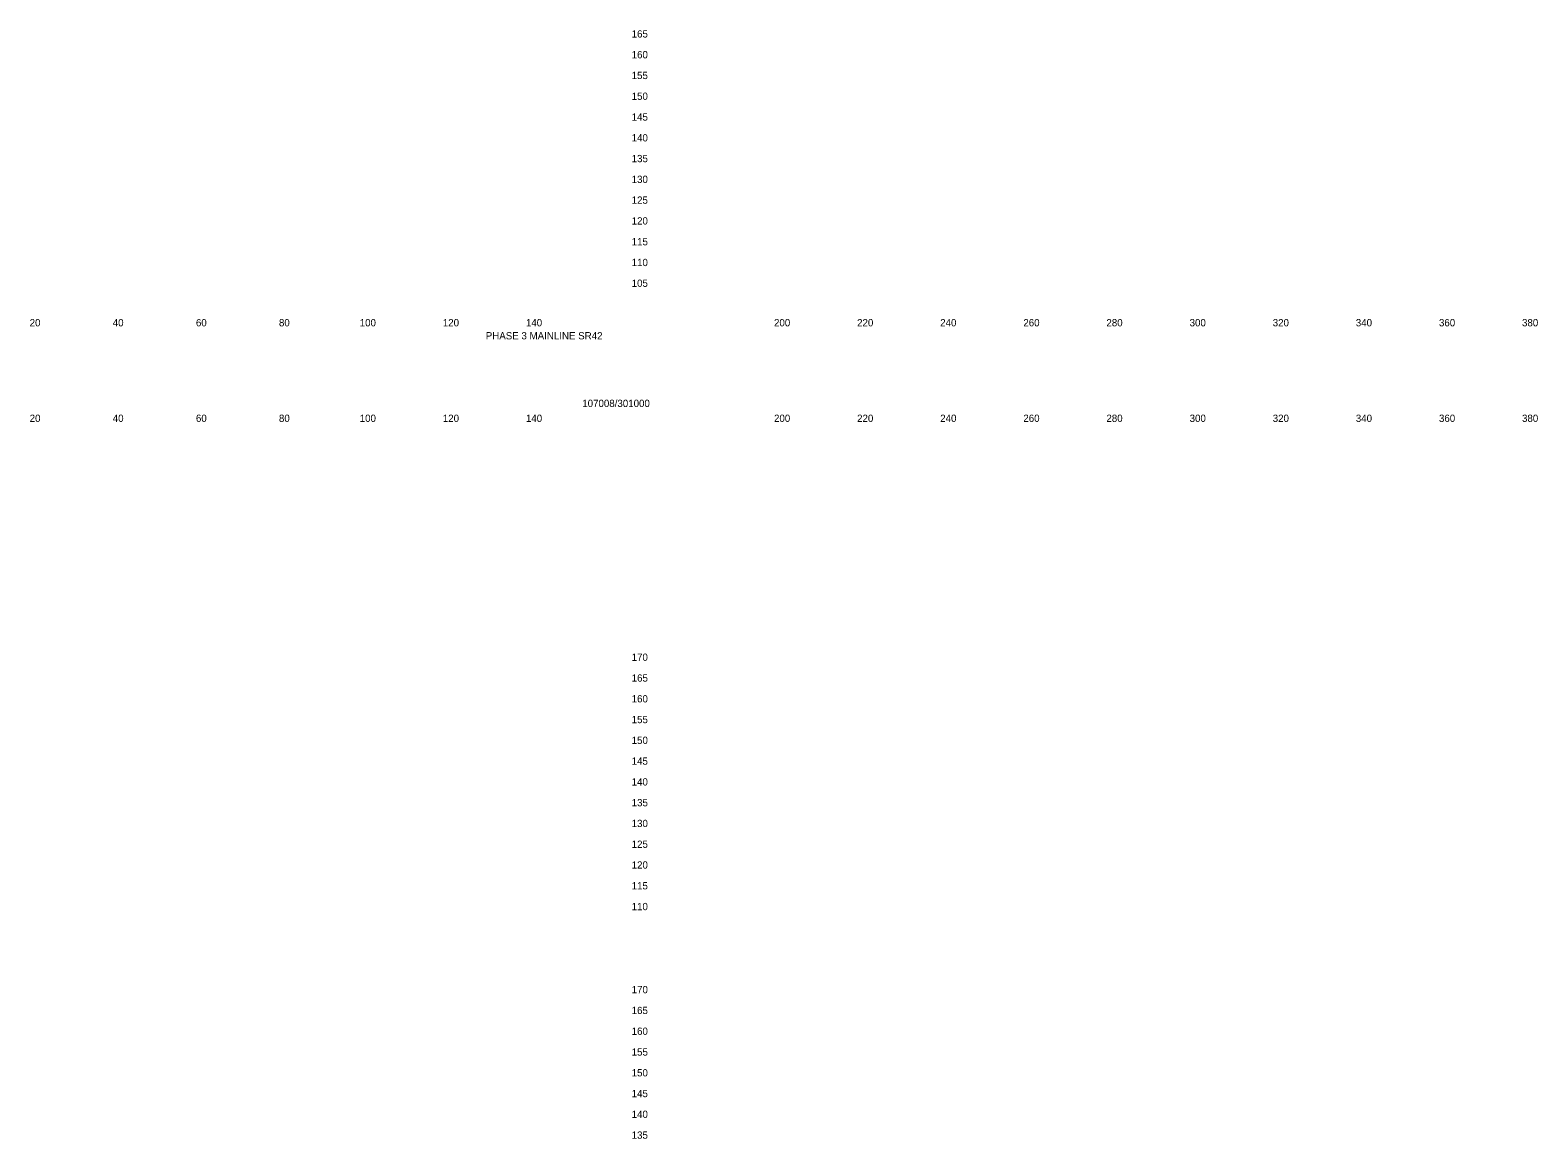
# Model space of a CAD drawing. Extents: x 21281 to 22024, y 6472 to 15198.
# Drawn here: x 21661.4 to 22024.2, y 11109.8 to 11376.6 of the extents above; entities that cross this region are included whole.
import ezdxf

# ---------------------------------------------------------------- set-up
doc = ezdxf.new("R2010")
doc.units = 0
doc.layers.add('Draft_XS_Grid', color=7, linetype='Continuous')
doc.layers.add('Draft_XS_Text', color=7, linetype='Continuous')

msp = doc.modelspace()

# ---------------------------------------------------------------- texts
at = {"layer": 'Draft_XS_Grid'}
for s, p in [('  165  ', (21804.84, 11374.84)), ('  160  ', (21804.84, 11369.84)), ('  155  ', (21804.84, 11364.84)), ('  150  ', (21804.84, 11359.84)), ('  145  ', (21804.84, 11354.84)), ('  140  ', (21804.84, 11349.84)), ('  135  ', (21804.84, 11344.84)), ('  130  ', (21804.84, 11339.84)), ('  125  ', (21804.84, 11334.84)), ('  120  ', (21804.84, 11329.84)), ('  115  ', (21804.84, 11324.84)), ('  110  ', (21804.84, 11319.84)), ('  105  ', (21804.84, 11314.84)), ('  170  ', (21804.84, 11224.84)), ('  165  ', (21804.84, 11219.84)), ('  160  ', (21804.84, 11214.84)), ('  155  ', (21804.84, 11209.84)), ('  150  ', (21804.84, 11204.84)), ('  145  ', (21804.84, 11199.84)), ('  140  ', (21804.84, 11194.84)), ('  135  ', (21804.84, 11189.84)), ('  130  ', (21804.84, 11184.84)), ('  125  ', (21804.84, 11179.84)), ('  120  ', (21804.84, 11174.84)), ('  115  ', (21804.84, 11169.84)), ('  110  ', (21804.84, 11164.84)), ('  170  ', (21804.84, 11144.84)), ('  165  ', (21804.84, 11139.84)), ('  160  ', (21804.84, 11134.84)), ('  155  ', (21804.84, 11129.84)), ('  150  ', (21804.84, 11124.84)), ('  145  ', (21804.84, 11119.84)), ('  140  ', (21804.84, 11114.84)), ('  135  ', (21804.84, 11109.84))]:
    msp.add_text(s, height=1.75, dxfattribs=at).set_placement(p)
at = {"layer": 'Draft_XS_Text'}
for s, p in [('  20  ', (21659.95, 11305.34)), ('  40  ', (21679.95, 11305.34)), ('  60  ', (21699.97, 11305.34)), ('  80  ', (21719.95, 11305.34)), ('  100  ', (21739.39, 11305.34)), ('  120  ', (21759.39, 11305.34)), ('  140  ', (21779.39, 11305.34)), ('  200  ', (21839.1, 11305.34)), ('  220  ', (21859.1, 11305.34)), ('  240  ', (21879.1, 11305.34)), ('  260  ', (21899.11, 11305.34)), ('  280  ', (21919.1, 11305.34)), ('  300  ', (21939.13, 11305.34)), ('  320  ', (21959.13, 11305.34)), ('  340  ', (21979.13, 11305.34)), ('  360  ', (21999.14, 11305.34)), ('  380  ', (22019.13, 11305.34)), ('PHASE 3 MAINLINE SR42', (21771.03, 11302.2)), ('107008/301000', (21794.25, 11285.93)), ('  20  ', (21659.95, 11282.34)), ('  40  ', (21679.95, 11282.34)), ('  60  ', (21699.97, 11282.34)), ('  80  ', (21719.95, 11282.34)), ('  100  ', (21739.39, 11282.34)), ('  120  ', (21759.39, 11282.34)), ('  140  ', (21779.39, 11282.34)), ('  200  ', (21839.1, 11282.34)), ('  220  ', (21859.1, 11282.34)), ('  240  ', (21879.1, 11282.34)), ('  260  ', (21899.11, 11282.34)), ('  280  ', (21919.1, 11282.34)), ('  300  ', (21939.13, 11282.34)), ('  320  ', (21959.13, 11282.34)), ('  340  ', (21979.13, 11282.34)), ('  360  ', (21999.14, 11282.34)), ('  380  ', (22019.13, 11282.34))]:
    msp.add_text(s, height=1.75, dxfattribs=at).set_placement(p)

doc.saveas('drawing.dxf')
